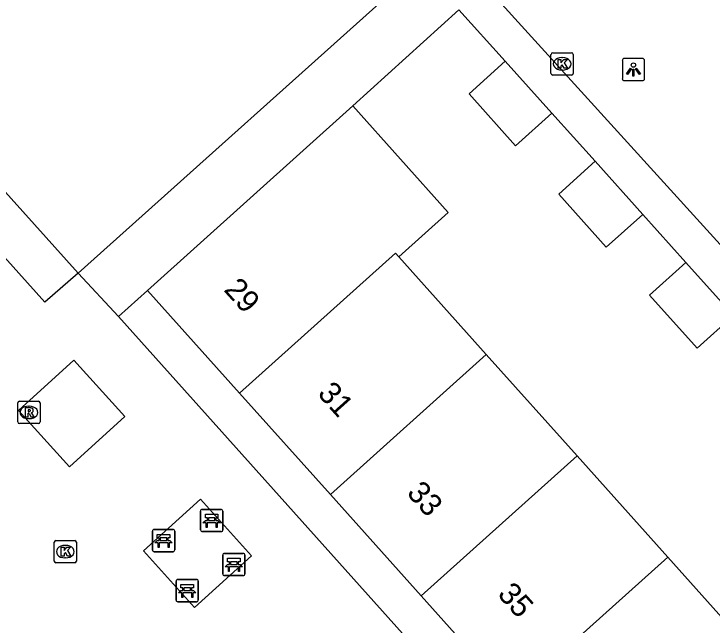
# Model space of a CAD drawing. Extents: x 162172 to 163187, y 382874 to 383684.
# Drawn here: x 162882.94 to 162914.31, y 383376.39 to 383403.85 of the extents above; entities that cross this region are included whole.
import ezdxf

# ---------------------------------------------------------------- set-up
doc = ezdxf.new("R2010")
doc.units = 0
for name, color, linetype in [('IMGEO_Bank', 7, 'Continuous'), ('IMGEO_Kolk', 7, 'Continuous'), ('IMGEO_Lichtpunt', 7, 'Continuous'), ('IMGEO_Pand', 7, 'Continuous'), ('IMGEO_Pand_nummerreeks', 7, 'Continuous'), ('IMGEO_Rioolput', 7, 'Continuous'), ('IMGEO_Voetpad_open', 7, 'Continuous')]:
    doc.layers.add(name, color=color, linetype=linetype)

msp = doc.modelspace()

# ---------------------------------------------------------------- linework, layer by layer
at = {"layer": 'IMGEO_Bank'}
for p, q in [((162891.322, 383380.665), (162891.322, 383381.506)), ((162891.322, 383381.506), (162891.322, 383380.665)), ((162891.397, 383381.59), (162892.238, 383381.59)), ((162892.238, 383381.59), (162891.397, 383381.59)), ((162892.322, 383381.515), (162892.322, 383380.674)), ((162892.322, 383380.674), (162892.322, 383381.515)), ((162891.631, 383381.096), (162891.631, 383381.202)), ((162891.675, 383381.202), (162891.675, 383381.096)), ((162891.963, 383381.208), (162891.681, 383381.208)), ((162891.969, 383381.096), (162891.969, 383381.202)), ((162892.013, 383381.202), (162892.013, 383381.096)), ((162892.019, 383380.988), (162891.626, 383380.988)), ((162891.681, 383381.09), (162891.963, 383381.09)), ((162889.16, 383379.765), (162889.16, 383380.606)), ((162889.16, 383380.606), (162889.16, 383379.765)), ((162889.235, 383380.69), (162890.076, 383380.69)), ((162890.076, 383380.69), (162889.235, 383380.69)), ((162890.16, 383380.615), (162890.16, 383379.774)), ((162890.16, 383379.774), (162890.16, 383380.615)), ((162892.247, 383380.59), (162891.406, 383380.59)), ((162891.406, 383380.59), (162892.247, 383380.59)), ((162889.469, 383380.196), (162889.469, 383380.302)), ((162889.513, 383380.302), (162889.513, 383380.196)), ((162889.801, 383380.308), (162889.519, 383380.308)), ((162889.807, 383380.196), (162889.807, 383380.302)), ((162889.851, 383380.302), (162889.851, 383380.196)), ((162889.857, 383380.088), (162889.464, 383380.088)), ((162889.519, 383380.19), (162889.801, 383380.19)), ((162890.085, 383379.69), (162889.244, 383379.69)), ((162889.244, 383379.69), (162890.085, 383379.69)), ((162892.318, 383378.689), (162892.318, 383379.53)), ((162892.318, 383379.53), (162892.318, 383378.689)), ((162892.393, 383379.614), (162893.234, 383379.614)), ((162893.234, 383379.614), (162892.393, 383379.614)), ((162893.318, 383379.539), (162893.318, 383378.698)), ((162893.318, 383378.698), (162893.318, 383379.539)), ((162893.015, 383379.012), (162892.622, 383379.012)), ((162892.627, 383379.12), (162892.627, 383379.226)), ((162892.671, 383379.226), (162892.671, 383379.12)), ((162892.959, 383379.232), (162892.677, 383379.232)), ((162892.677, 383379.114), (162892.959, 383379.114)), ((162892.965, 383379.12), (162892.965, 383379.226)), ((162893.009, 383379.226), (162893.009, 383379.12)), ((162890.297, 383378.442), (162891.138, 383378.442)), ((162891.138, 383378.442), (162890.297, 383378.442)), ((162891.222, 383378.367), (162891.222, 383377.526)), ((162891.222, 383377.526), (162891.222, 383378.367)), ((162893.243, 383378.614), (162892.402, 383378.614)), ((162892.402, 383378.614), (162893.243, 383378.614)), ((162890.222, 383377.517), (162890.222, 383378.358)), ((162890.222, 383378.358), (162890.222, 383377.517)), ((162890.531, 383377.948), (162890.531, 383378.054)), ((162890.575, 383378.054), (162890.575, 383377.948)), ((162890.863, 383378.06), (162890.581, 383378.06)), ((162890.869, 383377.948), (162890.869, 383378.054)), ((162890.913, 383378.054), (162890.913, 383377.948)), ((162890.919, 383377.84), (162890.526, 383377.84)), ((162890.581, 383377.942), (162890.863, 383377.942)), ((162891.147, 383377.442), (162890.306, 383377.442)), ((162890.306, 383377.442), (162891.147, 383377.442))]:
    msp.add_line(p, q, dxfattribs=at)
for points in [[(162891.625, 383381.208), (162891.539, 383381.208), (162891.539, 383381.369), (162892.102, 383381.369), (162892.102, 383381.208), (162892.019, 383381.208)], [(162891.569, 383380.988), (162891.427, 383380.988), (162891.539, 383381.09), (162891.625, 383381.09)], [(162891.619, 383380.981), (162891.619, 383380.774), (162891.576, 383380.774), (162891.576, 383380.981)], [(162892.019, 383381.09), (162892.102, 383381.09), (162892.214, 383380.988), (162892.075, 383380.988)], [(162892.069, 383380.981), (162892.069, 383380.774), (162892.025, 383380.774), (162892.025, 383380.981)], [(162889.463, 383380.308), (162889.377, 383380.308), (162889.377, 383380.469), (162889.94, 383380.469), (162889.94, 383380.308), (162889.857, 383380.308)], [(162889.407, 383380.088), (162889.265, 383380.088), (162889.377, 383380.19), (162889.463, 383380.19)], [(162889.457, 383380.081), (162889.457, 383379.874), (162889.414, 383379.874), (162889.414, 383380.081)], [(162889.857, 383380.19), (162889.94, 383380.19), (162890.052, 383380.088), (162889.913, 383380.088)], [(162889.907, 383380.081), (162889.907, 383379.874), (162889.863, 383379.874), (162889.863, 383380.081)], [(162892.621, 383379.232), (162892.535, 383379.232), (162892.535, 383379.393), (162893.098, 383379.393), (162893.098, 383379.232), (162893.015, 383379.232)], [(162892.565, 383379.012), (162892.423, 383379.012), (162892.535, 383379.114), (162892.621, 383379.114)], [(162892.615, 383379.005), (162892.615, 383378.798), (162892.572, 383378.798), (162892.572, 383379.005)], [(162893.015, 383379.114), (162893.098, 383379.114), (162893.21, 383379.012), (162893.071, 383379.012)], [(162893.065, 383379.005), (162893.065, 383378.798), (162893.021, 383378.798), (162893.021, 383379.005)], [(162890.525, 383378.06), (162890.439, 383378.06), (162890.439, 383378.221), (162891.002, 383378.221), (162891.002, 383378.06), (162890.919, 383378.06)], [(162890.469, 383377.84), (162890.327, 383377.84), (162890.439, 383377.942), (162890.525, 383377.942)], [(162890.519, 383377.833), (162890.519, 383377.626), (162890.476, 383377.626), (162890.476, 383377.833)], [(162890.919, 383377.942), (162891.002, 383377.942), (162891.114, 383377.84), (162890.975, 383377.84)], [(162890.969, 383377.833), (162890.969, 383377.626), (162890.925, 383377.626), (162890.925, 383377.833)]]:
    msp.add_lwpolyline(points, dxfattribs=at)
for centre, radius, start, end in [((162891.4, 383381.512), 0.0779, 92.4484, 184.2845), ((162891.4, 383381.512), 0.0779, 92.4484, 184.2845), ((162892.244, 383381.512), 0.0779, 2.4484, 94.2845), ((162892.244, 383381.512), 0.0779, 2.4484, 94.2845), ((162891.624, 383381.201), 0.00671, 2.8957, 87.1043), ((162891.681, 383381.201), 0.00671, 92.8957, 177.1043), ((162891.963, 383381.201), 0.00671, 2.8957, 87.1043), ((162892.02, 383381.201), 0.00671, 92.8957, 177.1043), ((162891.569, 383380.981), 0.00671, 2.8957, 87.1043), ((162891.626, 383380.981), 0.00671, 92.8957, 177.1043), ((162891.624, 383381.097), 0.00671, 272.8957, 357.1043), ((162891.681, 383381.097), 0.00671, 182.8957, 267.1043), ((162891.963, 383381.097), 0.00671, 272.8957, 357.1043), ((162892.02, 383381.097), 0.00671, 182.8957, 267.1043), ((162892.018, 383380.981), 0.00671, 2.8957, 87.1043), ((162892.075, 383380.981), 0.00671, 92.8957, 177.1043), ((162889.238, 383380.612), 0.0779, 92.4484, 184.2845), ((162889.238, 383380.612), 0.0779, 92.4484, 184.2845), ((162890.082, 383380.612), 0.0779, 2.4484, 94.2845), ((162890.082, 383380.612), 0.0779, 2.4484, 94.2845), ((162891.4, 383380.668), 0.0779, 182.4484, 274.2845), ((162891.4, 383380.668), 0.0779, 182.4484, 274.2845), ((162892.244, 383380.668), 0.0779, 272.4484, 4.2845), ((162892.244, 383380.668), 0.0779, 272.4484, 4.2845), ((162889.462, 383380.301), 0.00671, 2.8957, 87.1043), ((162889.519, 383380.301), 0.00671, 92.8957, 177.1043), ((162889.801, 383380.301), 0.00671, 2.8957, 87.1043), ((162889.858, 383380.301), 0.00671, 92.8957, 177.1043), ((162889.407, 383380.081), 0.00671, 2.8957, 87.1043), ((162889.464, 383380.081), 0.00671, 92.8957, 177.1043), ((162889.462, 383380.197), 0.00671, 272.8957, 357.1043), ((162889.519, 383380.197), 0.00671, 182.8957, 267.1043), ((162889.801, 383380.197), 0.00671, 272.8957, 357.1043), ((162889.858, 383380.197), 0.00671, 182.8957, 267.1043), ((162889.856, 383380.081), 0.00671, 2.8957, 87.1043), ((162889.913, 383380.081), 0.00671, 92.8957, 177.1043), ((162889.238, 383379.768), 0.0779, 182.4484, 274.2845), ((162889.238, 383379.768), 0.0779, 182.4484, 274.2845), ((162890.082, 383379.768), 0.0779, 272.4484, 4.2845), ((162890.082, 383379.768), 0.0779, 272.4484, 4.2845), ((162892.396, 383379.536), 0.0779, 92.4484, 184.2845), ((162892.396, 383379.536), 0.0779, 92.4484, 184.2845), ((162893.24, 383379.536), 0.0779, 2.4484, 94.2845), ((162893.24, 383379.536), 0.0779, 2.4484, 94.2845), ((162892.565, 383379.005), 0.00671, 2.8957, 87.1043), ((162892.622, 383379.005), 0.00671, 92.8957, 177.1043), ((162892.62, 383379.225), 0.00671, 2.8957, 87.1043), ((162892.62, 383379.121), 0.00671, 272.8957, 357.1043), ((162892.677, 383379.225), 0.00671, 92.8957, 177.1043), ((162892.677, 383379.121), 0.00671, 182.8957, 267.1043), ((162892.959, 383379.225), 0.00671, 2.8957, 87.1043), ((162892.959, 383379.121), 0.00671, 272.8957, 357.1043), ((162893.016, 383379.225), 0.00671, 92.8957, 177.1043), ((162893.016, 383379.121), 0.00671, 182.8957, 267.1043), ((162893.014, 383379.005), 0.00671, 2.8957, 87.1043), ((162893.071, 383379.005), 0.00671, 92.8957, 177.1043), ((162892.396, 383378.692), 0.0779, 182.4484, 274.2845), ((162892.396, 383378.692), 0.0779, 182.4484, 274.2845), ((162893.24, 383378.692), 0.0779, 272.4484, 4.2845), ((162893.24, 383378.692), 0.0779, 272.4484, 4.2845), ((162890.3, 383378.364), 0.0779, 92.4484, 184.2845), ((162890.3, 383378.364), 0.0779, 92.4484, 184.2845), ((162891.144, 383378.364), 0.0779, 2.4484, 94.2845), ((162891.144, 383378.364), 0.0779, 2.4484, 94.2845), ((162890.524, 383378.053), 0.00671, 2.8957, 87.1043), ((162890.581, 383378.053), 0.00671, 92.8957, 177.1043), ((162890.863, 383378.053), 0.00671, 2.8957, 87.1043), ((162890.92, 383378.053), 0.00671, 92.8957, 177.1043), ((162890.469, 383377.833), 0.00671, 2.8957, 87.1043), ((162890.526, 383377.833), 0.00671, 92.8957, 177.1043), ((162890.524, 383377.949), 0.00671, 272.8957, 357.1043), ((162890.581, 383377.949), 0.00671, 182.8957, 267.1043), ((162890.863, 383377.949), 0.00671, 272.8957, 357.1043), ((162890.92, 383377.949), 0.00671, 182.8957, 267.1043), ((162890.918, 383377.833), 0.00671, 2.8957, 87.1043), ((162890.975, 383377.833), 0.00671, 92.8957, 177.1043), ((162890.3, 383377.52), 0.0779, 182.4484, 274.2845), ((162890.3, 383377.52), 0.0779, 182.4484, 274.2845), ((162891.144, 383377.52), 0.0779, 272.4484, 4.2845), ((162891.144, 383377.52), 0.0779, 272.4484, 4.2845)]:
    msp.add_arc(centre, radius, start, end, dxfattribs=at)
at = {"layer": 'IMGEO_Kolk'}
for p, q in [((162907.071, 383401.179), (162907.071, 383402.031)), ((162907.146, 383402.105), (162907.998, 383402.105)), ((162908.072, 383402.031), (162908.072, 383401.179)), ((162907.559, 383401.885), (162907.584, 383401.885)), ((162907.582, 383401.325), (162907.557, 383401.325)), ((162907.998, 383401.105), (162907.146, 383401.105)), ((162884.743, 383379.266), (162884.743, 383380.118)), ((162884.818, 383380.192), (162885.67, 383380.192)), ((162885.231, 383379.972), (162885.256, 383379.972)), ((162885.744, 383380.118), (162885.744, 383379.266)), ((162885.254, 383379.412), (162885.229, 383379.412)), ((162885.67, 383379.192), (162884.818, 383379.192))]:
    msp.add_line(p, q, dxfattribs=at)
for points in [[(162907.071, 383401.179), (162907.071, 383402.031)], [(162907.146, 383402.105), (162907.998, 383402.105)], [(162908.072, 383402.031), (162908.072, 383401.179)], [(162907.392, 383401.805), (162907.515, 383401.805), (162907.515, 383401.654), (162907.645, 383401.805), (162907.809, 383401.805), (162907.663, 383401.654), (162907.816, 383401.405), (162907.664, 383401.405), (162907.579, 383401.569), (162907.515, 383401.502), (162907.515, 383401.405), (162907.392, 383401.405), (162907.392, 383401.805)], [(162907.998, 383401.105), (162907.146, 383401.105)], [(162884.743, 383379.266), (162884.743, 383380.118)], [(162884.818, 383380.192), (162885.67, 383380.192)], [(162885.744, 383380.118), (162885.744, 383379.266)], [(162885.064, 383379.892), (162885.187, 383379.892), (162885.187, 383379.741), (162885.317, 383379.892), (162885.481, 383379.892), (162885.335, 383379.741), (162885.488, 383379.492), (162885.336, 383379.492), (162885.251, 383379.656), (162885.187, 383379.589), (162885.187, 383379.492), (162885.064, 383379.492), (162885.064, 383379.892)], [(162885.67, 383379.192), (162884.818, 383379.192)]]:
    msp.add_lwpolyline(points, dxfattribs=at)
for centre, start, end in [((162907.148, 383402.029), 91.552, 178.448), ((162907.148, 383402.029), 91.552, 178.448), ((162907.996, 383402.029), 1.552, 88.448), ((162907.996, 383402.029), 1.552, 88.448), ((162907.148, 383401.181), 181.552, 268.448), ((162907.148, 383401.181), 181.552, 268.448), ((162907.996, 383401.181), 271.552, 358.448), ((162907.996, 383401.181), 271.552, 358.448), ((162884.82, 383380.116), 91.552, 178.448), ((162884.82, 383380.116), 91.552, 178.448), ((162885.668, 383380.116), 1.552, 88.448), ((162885.668, 383380.116), 1.552, 88.448), ((162884.82, 383379.268), 181.552, 268.448), ((162884.82, 383379.268), 181.552, 268.448), ((162885.668, 383379.268), 271.552, 358.448), ((162885.668, 383379.268), 271.552, 358.448)]:
    msp.add_arc(centre, 0.0765, start, end, dxfattribs=at)
for centre, major_axis, ratio, start_param, end_param in [((162907.558, 383401.605), (-0.387, 0.002), 0.722429, 4.712389, 7.853982), ((162907.583, 383401.605), (-0.39, 0.002), 0.717154, 1.570796, 4.712389), ((162885.23, 383379.692), (-0.387, 0.002), 0.722429, 4.712389, 7.853982), ((162885.255, 383379.692), (-0.39, 0.002), 0.717154, 1.570796, 4.712389)]:
    msp.add_ellipse(centre, major_axis=major_axis, ratio=ratio, start_param=start_param, end_param=end_param, dxfattribs=at)
at = {"layer": 'IMGEO_Lichtpunt'}
for p, q in [((162910.277, 383401.753), (162910.277, 383400.946)), ((162910.277, 383401.753), (162910.277, 383400.946)), ((162911.179, 383401.848), (162910.371, 383401.848)), ((162911.179, 383401.848), (162910.371, 383401.848)), ((162911.273, 383400.946), (162911.273, 383401.753)), ((162911.273, 383400.946), (162911.273, 383401.753)), ((162910.371, 383400.852), (162911.179, 383400.852)), ((162910.371, 383400.852), (162911.179, 383400.852))]:
    msp.add_line(p, q, dxfattribs=at)
for points in [[(162910.651, 383401.417), (162910.69, 383401.389), (162910.502, 383401.127), (162910.464, 383401.154), (162910.651, 383401.417)], [(162910.753, 383401.369), (162910.8, 383401.369), (162910.8, 383401.047), (162910.753, 383401.047), (162910.753, 383401.369)], [(162910.863, 383401.389), (162910.901, 383401.416), (162911.088, 383401.154), (162911.049, 383401.126), (162910.863, 383401.389)]]:
    msp.add_lwpolyline(points, dxfattribs=at)
msp.add_circle((162910.776, 383401.551), 0.0994, dxfattribs=at)
for centre, start, end in [((162910.371, 383401.753), 90, 180), ((162910.371, 383401.753), 90, 180), ((162911.179, 383401.753), 0, 90), ((162911.179, 383401.753), 0, 90), ((162910.371, 383400.946), 180, 270), ((162910.371, 383400.946), 180, 270), ((162911.179, 383400.946), 270, 0), ((162911.179, 383400.946), 270, 360)]:
    msp.add_arc(centre, 0.0946, start, end, dxfattribs=at)
at = {"layer": 'IMGEO_Pand'}
for points in [[(162869.056, 383410.879), (162885.821, 383392.207)], [(162896.86, 383410.818), (162901.2, 383405.989), (162885.821, 383392.207)], [(162907.113, 383399.395), (162905.476, 383397.927), (162903.386, 383400.258), (162905.017, 383401.733)], [(162905.017, 383401.733), (162907.113, 383399.395)], [(162888.938, 383391.424), (162898.159, 383399.714)], [(162898.159, 383399.714), (162902.454, 383394.929), (162900.234, 383392.929)], [(162911.193, 383394.845), (162909.556, 383393.377), (162907.42, 383395.759), (162909.057, 383397.227)], [(162909.057, 383397.227), (162911.193, 383394.845)], [(162900.234, 383392.929), (162900.086, 383393.094), (162893.077, 383386.809)], [(162900.234, 383392.929), (162904.163, 383388.542)], [(162915.273, 383390.294), (162913.636, 383388.826), (162911.5, 383391.208), (162913.137, 383392.676)], [(162913.137, 383392.676), (162915.273, 383390.294)], [(162893.077, 383386.809), (162888.938, 383391.424)], [(162897.157, 383382.259), (162904.163, 383388.542)], [(162904.163, 383388.542), (162908.241, 383383.989)], [(162897.157, 383382.259), (162893.077, 383386.809)], [(162908.241, 383383.989), (162901.238, 383377.709)], [(162908.241, 383383.989), (162912.319, 383379.437)], [(162901.238, 383377.709), (162897.157, 383382.259)], [(162905.318, 383373.159), (162912.319, 383379.437)], [(162912.319, 383379.437), (162916.396, 383374.884)], [(162905.318, 383373.159), (162901.238, 383377.709)]]:
    msp.add_lwpolyline(points, dxfattribs=at)
at = {"layer": 'IMGEO_Rioolput'}
for p, q in [((162883.109, 383385.522), (162883.109, 383386.374)), ((162883.184, 383386.448), (162884.036, 383386.448)), ((162883.597, 383386.228), (162883.622, 383386.228)), ((162884.11, 383386.374), (162884.11, 383385.522)), ((162883.62, 383385.668), (162883.595, 383385.668)), ((162884.036, 383385.448), (162883.184, 383385.448))]:
    msp.add_line(p, q, dxfattribs=at)
for points in [[(162883.109, 383385.522), (162883.109, 383386.374)], [(162883.184, 383386.448), (162884.036, 383386.448)], [(162884.11, 383386.374), (162884.11, 383385.522)], [(162883.698, 383386.146), (162883.446, 383386.148), (162883.446, 383385.748)], [(162883.446, 383385.748), (162883.57, 383385.748), (162883.57, 383385.91), (162883.581, 383385.91)], [(162883.624, 383386.067), (162883.57, 383386.067), (162883.57, 383385.986)], [(162883.57, 383385.986), (162883.622, 383385.986)], [(162883.628, 383385.881), (162883.699, 383385.748), (162883.839, 383385.748), (162883.774, 383385.874)], [(162884.036, 383385.448), (162883.184, 383385.448)]]:
    msp.add_lwpolyline(points, dxfattribs=at)
for centre, radius, start, end in [((162883.186, 383386.372), 0.0765, 91.552, 178.448), ((162883.186, 383386.372), 0.0765, 91.552, 178.448), ((162884.034, 383386.372), 0.0765, 1.552, 88.448), ((162884.034, 383386.372), 0.0765, 1.552, 88.448), ((162883.58, 383385.857), 0.0533, 26.0293, 88.6989), ((162883.606, 383386.175), 0.19, 274.7715, 282.9687), ((162883.63, 383385.971), 0.0964, 77.0061, 93.1865), ((162883.644, 383386.028), 0.0378, 276.6634, 79.6772), ((162883.697, 383386.036), 0.109, 350.3612, 89.416), ((162883.695, 383386.036), 0.112, 277.5842, 350.9817), ((162883.679, 383385.821), 0.108, 29.5134, 73.7905), ((162883.186, 383385.524), 0.0765, 181.552, 268.448), ((162883.186, 383385.524), 0.0765, 181.552, 268.448), ((162884.034, 383385.524), 0.0765, 271.552, 358.448), ((162884.034, 383385.524), 0.0765, 271.552, 358.448)]:
    msp.add_arc(centre, radius, start, end, dxfattribs=at)
for centre, major_axis, ratio, start_param, end_param in [((162883.596, 383385.948), (-0.387, 0.002), 0.722429, 4.712389, 7.853982), ((162883.621, 383385.948), (-0.39, 0.002), 0.717154, 1.570796, 4.712389)]:
    msp.add_ellipse(centre, major_axis=major_axis, ratio=ratio, start_param=start_param, end_param=end_param, dxfattribs=at)
at = {"layer": 'IMGEO_Voetpad_open'}
for points in [[(162979.85, 383448.242), (162970.83, 383440.134), (162946.141, 383417.88), (162945.417, 383418.688), (162915.853, 383392.195), (162902.485, 383406.92), (162904.191, 383408.453), (162900.798, 383412.235), (162900.891, 383412.317), (162939.367, 383446.841), (162950.025, 383434.963)], [(162885.821, 383392.207), (162884.33, 383390.898), (162867.584, 383409.558), (162869.056, 383410.879)], [(162898.159, 383399.714), (162902.923, 383404.039), (162905.017, 383401.733)], [(162907.113, 383399.395), (162909.057, 383397.227)], [(162911.193, 383394.845), (162913.137, 383392.676)], [(162885.821, 383392.207), (162887.637, 383390.257)], [(162887.637, 383390.257), (162888.938, 383391.424)], [(162916.26, 383358.318), (162887.637, 383390.257)], [(162885.425, 383383.495), (162883.134, 383386.028), (162885.634, 383388.289), (162887.925, 383385.756), (162885.425, 383383.495)], [(162891.055, 383377.185), (162888.752, 383379.734), (162891.313, 383382.047), (162893.616, 383379.498), (162891.055, 383377.185)]]:
    msp.add_lwpolyline(points, dxfattribs=at)

# ---------------------------------------------------------------- texts
at = {"layer": 'IMGEO_Pand_nummerreeks'}
for s, rotation, p in [('29', 312.1835, (162892.332, 383391.432)), ('31', 311.8827, (162896.541, 383386.768)), ('33', 311.8897, (162900.548, 383382.301)), ('35', 311.8827, (162904.628, 383377.751))]:
    msp.add_text(s, height=1, rotation=rotation, dxfattribs=at).set_placement(p)

doc.saveas('drawing.dxf')
